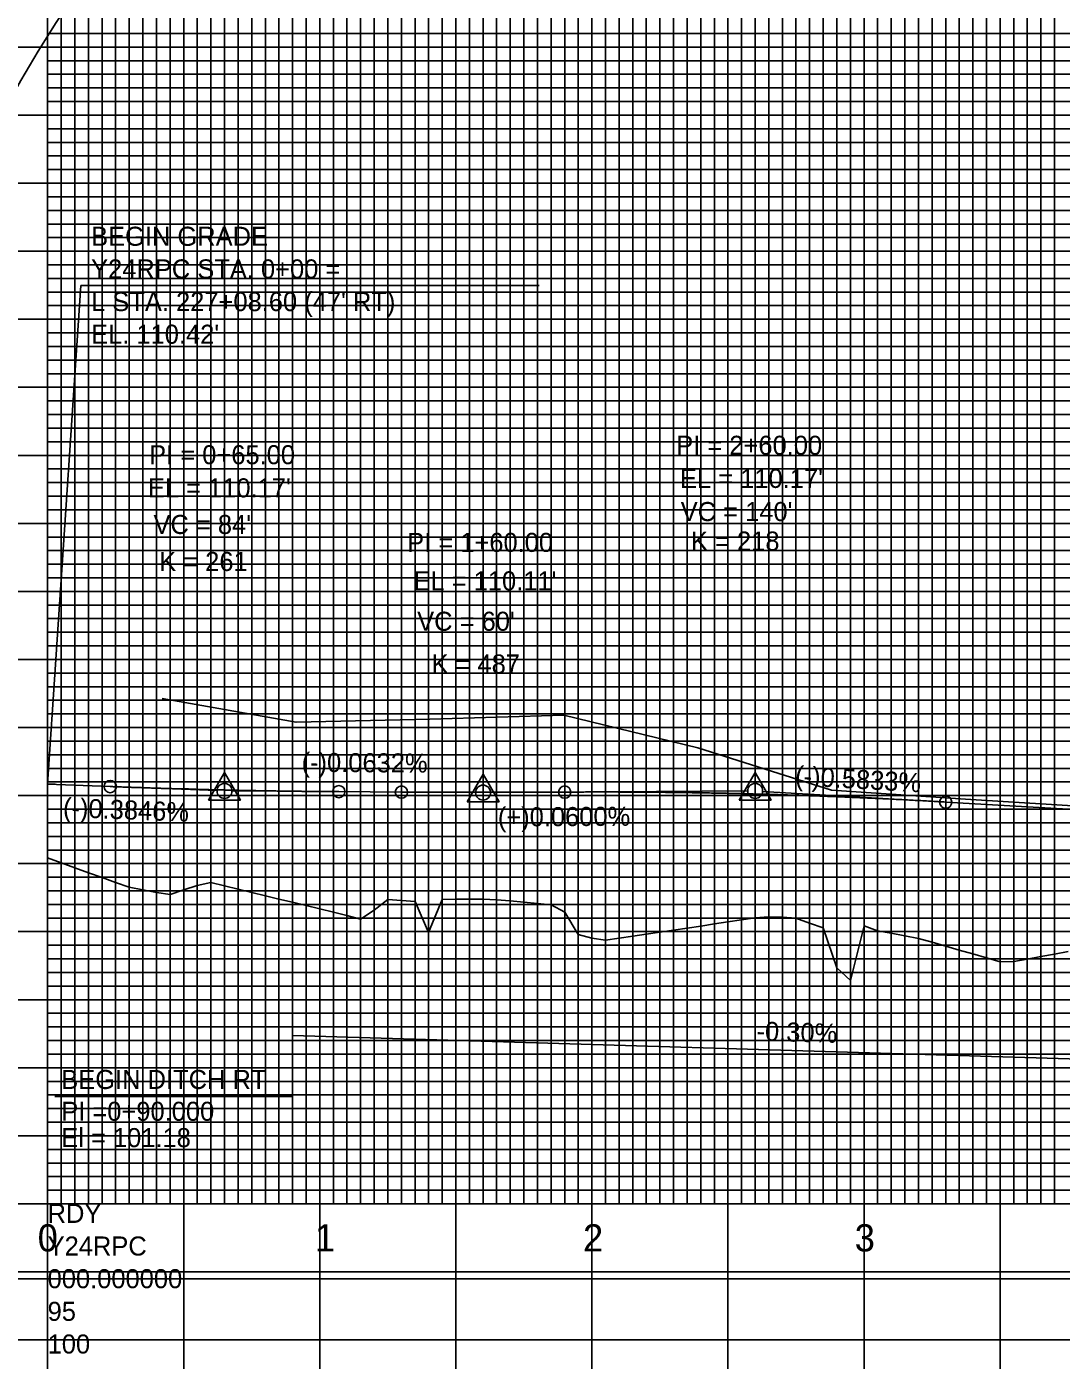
# Model space of a CAD drawing. Extents: x 2345490 to 2445302, y 465165 to 573888.
# Drawn here: x 2410887.6 to 2411267.8, y 527714.5 to 528204.5 of the extents above; entities that cross this region are included whole.
import ezdxf

# ---------------------------------------------------------------- set-up
doc = ezdxf.new("R2010")
doc.units = 0
for name, color, linetype in [('Old_Level_1', 7, 'Continuous'), ('Old_Level_18', 7, 'Continuous'), ('Old_Level_2', 7, 'Continuous'), ('Old_Level_3', 7, 'Continuous'), ('Old_Level_41', 7, 'Continuous'), ('Old_Level_42', 7, 'Continuous'), ('Old_Level_43', 7, 'Continuous'), ('Old_Level_50', 7, 'Continuous'), ('Old_Level_51', 7, 'Continuous'), ('Old_Level_62', 7, 'Continuous'), ('Old_Level_63', 7, 'Continuous')]:
    doc.layers.add(name, color=color, linetype=linetype)

msp = doc.modelspace()

# ---------------------------------------------------------------- linework, layer by layer
at = {"layer": 'Old_Level_1'}
msp.add_lwpolyline([(2410895.325, 527899.13175), (2410900.325, 527897.31625), (2410905.325, 527895.5035), (2410910.325, 527893.693), (2410915.325, 527891.885), (2410920.325, 527890.0795), (2410925.325, 527888.346), (2410930.325, 527887.3755), (2410935.325, 527886.411), (2410940.325, 527885.72725), (2410945.325, 527887.3925), (2410950.325, 527889.05825), (2410955.325, 527890.15175), (2410960.325, 527888.925), (2410965.325, 527887.7005), (2410970.325, 527886.47775), (2410975.325, 527885.2575), (2410980.325, 527884.03925), (2410985.325, 527882.82325), (2410990.325, 527881.60975), (2410995.325, 527880.3985), (2411000.325, 527879.18975), (2411005.325, 527877.93375), (2411010.325, 527876.6665), (2411015.325, 527879.893), (2411020.325, 527883.87575), (2411025.325, 527883.503), (2411030.325, 527883.133), (2411035.325, 527871.77675), (2411040.325, 527883.91325), (2411045.325, 527883.91925), (2411050.325, 527883.92525), (2411055.325, 527883.93125), (2411060.325, 527883.73025), (2411065.325, 527883.311), (2411070.325, 527882.85025), (2411075.325, 527882.393), (2411080.325, 527881.93875), (2411085.325, 527879.234), (2411090.325, 527871.036), (2411095.325, 527869.64375), (2411100.325, 527868.95075), (2411105.325, 527869.67875), (2411110.325, 527870.41), (2411115.325, 527871.145), (2411120.325, 527871.88325), (2411125.325, 527872.625), (2411130.325, 527873.37025), (2411135.325, 527874.119), (2411140.325, 527874.871), (2411145.325, 527875.6265), (2411150.325, 527876.38525), (2411155.325, 527877.1475), (2411160.325, 527877.43575), (2411165.325, 527877.34625), (2411170.325, 527876.95475), (2411175.325, 527875.21325), (2411180.325, 527873.416), (2411185.325, 527858.70475), (2411190.325, 527854.09575), (2411195.325, 527874.16475), (2411200.325, 527872.31375), (2411205.325, 527871.48075), (2411210.325, 527870.51025), (2411215.325, 527869.54075), (2411220.325, 527868.19025), (2411225.325, 527866.74475), (2411230.325, 527865.29575), (2411235.325, 527863.8435), (2411240.325, 527862.38775), (2411245.325, 527860.92875), (2411250.325, 527861.044), (2411255.325, 527861.95825), (2411260.325, 527862.8805), (2411265.325, 527863.81025), (2411270.325, 527864.748)], dxfattribs=at)
at = {"layer": 'Old_Level_18'}
msp.add_lwpolyline([(2412345.325, 528797.04275), (2410845.325, 528797.04275), (2410845.325, 527747.04275), (2412345.325, 527747.04275)], close=True, dxfattribs=at)
at = {"layer": 'Old_Level_2'}
for p, q in [((2410907.5385, 528109.43), (2410895.325, 527926.24275)), ((2411076.005, 528109.43), (2410907.5385, 528109.43)), ((2410895.325, 527926.243), (2410918.32525, 527925.3585)), ((2410918.32525, 527925.3585), (2410957.57725, 527923.84875)), ((2411002.325, 527923.47775), (2410963.075, 527923.72575)), ((2411002.325, 527923.47775), (2411025.325, 527923.3325)), ((2411025.325, 527923.3325), (2411052.57525, 527923.1605)), ((2411085.325, 527923.323), (2411152.57525, 527923.72675)), ((2411225.32525, 527919.65975), (2411158.0705, 527923.583)), ((2411085.325, 527923.323), (2411058.075, 527923.1595)), ((2411225.32525, 527919.65975), (2411300.325, 527915.28475))]:
    msp.add_line(p, q, dxfattribs=at)
for points in [[(2410954.45375, 527920.36775), (2410966.19625, 527920.36775), (2410960.32525, 527930.4935)], [(2411049.45375, 527919.76775), (2411061.19625, 527919.76775), (2411055.32525, 527929.8935)], [(2411149.45375, 527920.36775), (2411161.19625, 527920.36775), (2411155.32525, 527930.4935)]]:
    msp.add_lwpolyline(points, close=True, dxfattribs=at)
for centre, radius in [((2410918.32525, 527925.3585), 2.25), ((2410960.325, 527923.743), 2.75), ((2411002.325, 527923.47775), 2.25), ((2411025.325, 527923.3325), 2.25), ((2411055.325, 527923.143), 2.75), ((2411085.325, 527923.323), 2.25), ((2411155.325, 527923.743), 2.75), ((2411225.32525, 527919.65975), 2.25)]:
    msp.add_circle(centre, radius, dxfattribs=at)
for points in [[(2410918.32525, 527925.3585), (2410920.00525, 527925.2945), (2410921.68525, 527925.2315), (2410923.36525, 527925.1695), (2410925.04525, 527925.10875), (2410926.72525, 527925.049), (2410928.40525, 527924.99025), (2410930.08525, 527924.93275), (2410931.76525, 527924.87625), (2410933.44525, 527924.82075), (2410935.12525, 527924.76625), (2410936.80525, 527924.713), (2410938.48525, 527924.661), (2410940.16525, 527924.60975), (2410941.84525, 527924.55975), (2410943.52525, 527924.51075), (2410945.20525, 527924.463), (2410946.88525, 527924.416), (2410948.56525, 527924.3705), (2410950.24525, 527924.32575), (2410951.92525, 527924.28225), (2410953.60525, 527924.23975), (2410955.28525, 527924.19825), (2410956.96525, 527924.158), (2410958.64525, 527924.11875), (2410960.325, 527924.08075), (2410962.005, 527924.0435), (2410963.685, 527924.0075), (2410965.365, 527923.97275), (2410967.045, 527923.93875), (2410968.725, 527923.906), (2410970.405, 527923.8745), (2410972.085, 527923.84375), (2410973.765, 527923.81425), (2410975.445, 527923.786), (2410977.125, 527923.7585), (2410978.805, 527923.73225), (2410980.485, 527923.707), (2410982.165, 527923.683), (2410983.845, 527923.66), (2410985.525, 527923.638), (2410987.205, 527923.617), (2410988.885, 527923.59725), (2410990.565, 527923.5785), (2410992.245, 527923.561), (2410993.925, 527923.5445), (2410995.605, 527923.529), (2410997.285, 527923.5145), (2410998.965, 527923.50125), (2411000.645, 527923.489), (2411002.325, 527923.47775)], [(2411025.325, 527923.3325), (2411026.525, 527923.32525), (2411027.725, 527923.318), (2411028.925, 527923.31125), (2411030.125, 527923.30475), (2411031.325, 527923.2985), (2411032.525, 527923.2925), (2411033.725, 527923.28675), (2411034.925, 527923.2815), (2411036.125, 527923.27625), (2411037.325, 527923.2715), (2411038.525, 527923.267), (2411039.725, 527923.263), (2411040.925, 527923.259), (2411042.125, 527923.2555), (2411043.325, 527923.25225), (2411044.525, 527923.24925), (2411045.725, 527923.2465), (2411046.925, 527923.244), (2411048.125, 527923.242), (2411049.325, 527923.24025), (2411050.525, 527923.2385), (2411051.725, 527923.2375), (2411052.925, 527923.2365), (2411054.125, 527923.23575), (2411055.325, 527923.2355), (2411056.525, 527923.2355), (2411057.725, 527923.23575), (2411058.925, 527923.23625), (2411060.125, 527923.237), (2411061.325, 527923.23825), (2411062.525, 527923.23975), (2411063.725, 527923.2415), (2411064.925, 527923.2435), (2411066.125, 527923.24575), (2411067.325, 527923.2485), (2411068.525, 527923.25125), (2411069.725, 527923.2545), (2411070.925, 527923.258), (2411072.125, 527923.26175), (2411073.325, 527923.266), (2411074.525, 527923.27025), (2411075.725, 527923.275), (2411076.925, 527923.28), (2411078.125, 527923.28525), (2411079.325, 527923.29075), (2411080.525, 527923.29675), (2411081.725, 527923.30275), (2411082.925, 527923.30925), (2411084.125, 527923.316), (2411085.325, 527923.323)], [(2411085.325, 527923.323), (2411088.125, 527923.338), (2411090.925, 527923.3495), (2411093.725, 527923.35725), (2411096.525, 527923.3615), (2411099.325, 527923.362), (2411102.125, 527923.359), (2411104.925, 527923.3525), (2411107.725, 527923.34225), (2411110.525, 527923.3285), (2411113.325, 527923.311), (2411116.125, 527923.29), (2411118.925, 527923.26525), (2411121.725, 527923.237), (2411124.525, 527923.20525), (2411127.325, 527923.16975), (2411130.125, 527923.13075), (2411132.925, 527923.08825), (2411135.725, 527923.042), (2411138.525, 527922.992), (2411141.325, 527922.9385), (2411144.125, 527922.8815), (2411146.925, 527922.821), (2411149.725, 527922.7565), (2411152.525, 527922.68875), (2411155.325, 527922.61725), (2411158.12525, 527922.54225), (2411160.92525, 527922.4635), (2411163.72525, 527922.38125), (2411166.52525, 527922.2955), (2411169.32525, 527922.206), (2411172.12525, 527922.11275), (2411174.92525, 527922.01625), (2411177.72525, 527921.91575), (2411180.52525, 527921.812), (2411183.32525, 527921.7045), (2411186.12525, 527921.5935), (2411188.92525, 527921.47875), (2411191.72525, 527921.3605), (2411194.52525, 527921.2385), (2411197.32525, 527921.113), (2411200.12525, 527920.984), (2411202.92525, 527920.85125), (2411205.72525, 527920.71475), (2411208.52525, 527920.575), (2411211.32525, 527920.4315), (2411214.12525, 527920.28425), (2411216.92525, 527920.1335), (2411219.72525, 527919.97925), (2411222.52525, 527919.82125), (2411225.32525, 527919.65975)]]:
    msp.add_spline(points, degree=3, dxfattribs=at)
at = {"layer": 'Old_Level_3'}
for p, q in [((2410895.325, 527772.04275), (2410895.325, 527842.4422)), ((2410895.325, 527842.4422), (2410895.325, 527600.73736)), ((2410985.325, 527833.84275), (2411407.325, 527821.24275)), ((2410985.325, 527833.84275), (2410985.32509, 527811.44435)), ((2410897.96027, 527811.44435), (2410985.32509, 527811.44435))]:
    msp.add_line(p, q, dxfattribs=at)
at = {"layer": 'Old_Level_41'}
msp.add_line((2412345.325, 527772.04275), (2410845.325, 527772.04275), dxfattribs=at)
for points in [[(2410895.325, 528797.04275), (2410895.325, 527772.04275), (2410945.325, 527772.04275), (2410945.325, 528797.04275)], [(2410920.325, 527772.04275), (2410920.325, 528797.04275)], [(2410970.325, 528797.04275), (2410970.325, 527772.04275), (2411020.325, 527772.04275), (2411020.325, 528797.04275)], [(2410995.325, 528797.04275), (2410995.325, 527772.04275), (2411045.325, 527772.04275), (2411045.325, 528797.04275)], [(2411070.325, 528797.04275), (2411070.325, 527772.04275), (2411120.325, 527772.04275), (2411120.325, 528797.04275)], [(2411095.325, 528797.04275), (2411095.325, 527772.04275), (2411145.325, 527772.04275), (2411145.325, 528797.04275)], [(2411170.325, 528797.04275), (2411170.325, 527772.04275), (2411220.325, 527772.04275), (2411220.325, 528797.04275)], [(2411195.325, 528797.04275), (2411195.325, 527772.04275), (2411245.325, 527772.04275), (2411245.325, 528797.04275)], [(2412345.325, 528197.04275), (2410845.325, 528197.04275), (2410845.325, 528147.04275), (2412345.325, 528147.04275)], [(2412345.325, 528122.04275), (2410845.325, 528122.04275), (2410845.325, 528172.04275), (2412345.325, 528172.04275)], [(2412345.325, 528097.04275), (2410845.325, 528097.04275), (2410845.325, 528047.04275), (2412345.325, 528047.04275)], [(2412345.325, 528022.04275), (2410845.325, 528022.04275), (2410845.325, 528072.04275), (2412345.325, 528072.04275)], [(2412345.325, 527997.04275), (2410845.325, 527997.04275), (2410845.325, 527947.04275), (2412345.325, 527947.04275)], [(2412345.325, 527897.04275), (2410845.325, 527897.04275), (2410845.325, 527847.04275), (2412345.325, 527847.04275)], [(2412345.325, 527822.04275), (2410845.325, 527822.04275), (2410845.325, 527872.04275), (2412345.325, 527872.04275)], [(2412345.325, 527797.04275), (2410845.325, 527797.04275)]]:
    msp.add_lwpolyline(points, dxfattribs=at)
at = {"layer": 'Old_Level_42'}
msp.add_lwpolyline([(2412345.325, 527922.04275), (2410845.325, 527922.04275), (2410845.325, 527972.04275), (2412345.325, 527972.04275)], dxfattribs=at)
at = {"layer": 'Old_Level_43'}
for points in [[(2410900.325, 528797.04275), (2410900.325, 527772.04275), (2410905.325, 527772.04275), (2410905.325, 528797.04275)], [(2410910.325, 528797.04275), (2410910.325, 527772.04275), (2410915.325, 527772.04275), (2410915.325, 528797.04275)], [(2410925.325, 528797.04275), (2410925.325, 527772.04275), (2410930.325, 527772.04275), (2410930.325, 528797.04275)], [(2410935.325, 528797.04275), (2410935.325, 527772.04275), (2410940.325, 527772.04275), (2410940.325, 528797.04275)], [(2410950.325, 528797.04275), (2410950.325, 527772.04275), (2410955.325, 527772.04275), (2410955.325, 528797.04275)], [(2410960.325, 528797.04275), (2410960.325, 527772.04275), (2410965.325, 527772.04275), (2410965.325, 528797.04275)], [(2410975.325, 528797.04275), (2410975.325, 527772.04275), (2410980.325, 527772.04275), (2410980.325, 528797.04275)], [(2410985.325, 528797.04275), (2410985.325, 527772.04275), (2410990.325, 527772.04275), (2410990.325, 528797.04275)], [(2411000.325, 528797.04275), (2411000.325, 527772.04275), (2411005.325, 527772.04275), (2411005.325, 528797.04275)], [(2411010.325, 528797.04275), (2411010.325, 527772.04275), (2411015.325, 527772.04275), (2411015.325, 528797.04275)], [(2411025.325, 528797.04275), (2411025.325, 527772.04275), (2411030.325, 527772.04275), (2411030.325, 528797.04275)], [(2411035.325, 528797.04275), (2411035.325, 527772.04275), (2411040.325, 527772.04275), (2411040.325, 528797.04275)], [(2411050.325, 528797.04275), (2411050.325, 527772.04275), (2411055.325, 527772.04275), (2411055.325, 528797.04275)], [(2411060.325, 527772.04275), (2411065.325, 527772.04275), (2411065.325, 528797.04275)], [(2411060.325, 528797.04275), (2411060.325, 527772.04275)], [(2411075.325, 528797.04275), (2411075.325, 527772.04275), (2411080.325, 527772.04275), (2411080.325, 528797.04275)], [(2411085.325, 528797.04275), (2411085.325, 527772.04275), (2411090.325, 527772.04275), (2411090.325, 528797.04275)], [(2411100.325, 528797.04275), (2411100.325, 527772.04275), (2411105.325, 527772.04275), (2411105.325, 528797.04275)], [(2411110.325, 528797.04275), (2411110.325, 527772.04275), (2411115.325, 527772.04275), (2411115.325, 528797.04275)], [(2411125.325, 528797.04275), (2411125.325, 527772.04275), (2411130.325, 527772.04275), (2411130.325, 528797.04275)], [(2411135.325, 528797.04275), (2411135.325, 527772.04275), (2411140.325, 527772.04275), (2411140.325, 528797.04275)], [(2411150.325, 528797.04275), (2411150.325, 527772.04275), (2411155.325, 527772.04275), (2411155.325, 528797.04275)], [(2411160.325, 528797.04275), (2411160.325, 527772.04275), (2411165.325, 527772.04275), (2411165.325, 528797.04275)], [(2411175.325, 528797.04275), (2411175.325, 527772.04275), (2411180.325, 527772.04275), (2411180.325, 528797.04275)], [(2411185.325, 528797.04275), (2411185.325, 527772.04275), (2411190.325, 527772.04275), (2411190.325, 528797.04275)], [(2411200.325, 528797.04275), (2411200.325, 527772.04275), (2411205.325, 527772.04275), (2411205.325, 528797.04275)], [(2411210.325, 528797.04275), (2411210.325, 527772.04275), (2411215.325, 527772.04275), (2411215.325, 528797.04275)], [(2411225.325, 528797.04275), (2411225.325, 527772.04275), (2411240.325, 527772.04275), (2411240.325, 528797.04275)], [(2411230.325, 528797.04275), (2411230.325, 527772.04275), (2411235.325, 527772.04275), (2411235.325, 528797.04275)], [(2411230.325, 528796.44275), (2411230.325, 527772.04275), (2411235.325, 527772.04275), (2411235.325, 528796.44275)], [(2411250.325, 528797.04275), (2411250.325, 527772.04275), (2411255.325, 527772.04275), (2411255.325, 528797.04275)], [(2411260.325, 528797.04275), (2411260.325, 527772.04275), (2411265.325, 527772.04275), (2411265.325, 528797.04275)], [(2412295.325, 528202.04275), (2410895.325, 528202.04275), (2410895.325, 528192.04275), (2412295.325, 528192.04275)], [(2412295.325, 528187.04275), (2410895.325, 528187.04275), (2410895.325, 528182.04275), (2412295.325, 528182.04275)], [(2412295.325, 528177.04275), (2410895.325, 528177.04275), (2410895.325, 528167.04275), (2412295.325, 528167.04275)], [(2412295.325, 528162.04275), (2410895.325, 528162.04275), (2410895.325, 528157.04275), (2412295.325, 528157.04275)], [(2412295.325, 528152.04275), (2410895.325, 528152.04275), (2410895.325, 528142.04275), (2412295.325, 528142.04275)], [(2412295.325, 528137.04275), (2410895.325, 528137.04275), (2410895.325, 528132.04275), (2412295.325, 528132.04275)], [(2412295.325, 528127.04275), (2410895.325, 528127.04275), (2410895.325, 528117.04275), (2412295.325, 528117.04275)], [(2412295.325, 528112.04275), (2410895.325, 528112.04275), (2410895.325, 528107.04275), (2412295.325, 528107.04275)], [(2412295.325, 528102.04275), (2410895.325, 528102.04275), (2410895.325, 528092.04275), (2412295.325, 528092.04275)], [(2412295.325, 528087.04275), (2410895.325, 528087.04275), (2410895.325, 528082.04275), (2412295.325, 528082.04275)], [(2412295.325, 528077.04275), (2410895.325, 528077.04275), (2410895.325, 528067.04275), (2412295.325, 528067.04275)], [(2412295.325, 528062.04275), (2410895.325, 528062.04275), (2410895.325, 528057.04275), (2412295.325, 528057.04275)], [(2412295.325, 528052.04275), (2410895.325, 528052.04275), (2410895.325, 528042.04275), (2412295.325, 528042.04275)], [(2412295.325, 528037.04275), (2410895.325, 528037.04275), (2410895.325, 528032.04275), (2412295.325, 528032.04275)], [(2412295.325, 528027.04275), (2410895.325, 528027.04275), (2410895.325, 528017.04275), (2412295.325, 528017.04275)], [(2412295.325, 528012.04275), (2410895.325, 528012.04275), (2410895.325, 528007.04275), (2412295.325, 528007.04275)], [(2412295.325, 528002.04275), (2410895.325, 528002.04275), (2410895.325, 527992.04275), (2412295.325, 527992.04275)], [(2412295.325, 527987.04275), (2410895.325, 527987.04275), (2410895.325, 527982.04275), (2412295.325, 527982.04275)], [(2412295.325, 527977.04275), (2410895.325, 527977.04275)], [(2410895.325, 527967.04275), (2412295.325, 527967.04275)], [(2412295.325, 527962.04275), (2410895.325, 527962.04275), (2410895.325, 527957.04275), (2412295.325, 527957.04275)], [(2412295.325, 527952.04275), (2410895.325, 527952.04275)], [(2410895.325, 527942.04275), (2412295.325, 527942.04275)], [(2412295.325, 527937.04275), (2410895.325, 527937.04275), (2410895.325, 527932.04275), (2412295.325, 527932.04275)], [(2412295.325, 527927.04275), (2410895.325, 527927.04275), (2410895.325, 527917.04275), (2412295.325, 527917.04275)], [(2412295.325, 527912.04275), (2410895.325, 527912.04275), (2410895.325, 527907.04275), (2412295.325, 527907.04275)], [(2412295.325, 527902.04275), (2410895.325, 527902.04275), (2410895.325, 527892.04275), (2412295.325, 527892.04275)], [(2412295.325, 527887.04275), (2410895.325, 527887.04275), (2410895.325, 527882.04275), (2412295.325, 527882.04275)], [(2412295.325, 527877.04275), (2410895.325, 527877.04275), (2410895.325, 527867.04275), (2412295.325, 527867.04275)], [(2412295.325, 527862.04275), (2410895.325, 527862.04275), (2410895.325, 527857.04275), (2412295.325, 527857.04275)], [(2412295.325, 527852.04275), (2410895.325, 527852.04275), (2410895.325, 527842.04275), (2412295.325, 527842.04275)], [(2412295.325, 527837.04275), (2410895.325, 527837.04275), (2410895.325, 527832.04275), (2412295.325, 527832.04275)], [(2412295.325, 527827.04275), (2410895.325, 527827.04275), (2410895.325, 527817.04275), (2412295.325, 527817.04275)], [(2412295.325, 527812.04275), (2410895.325, 527812.04275), (2410895.325, 527807.04275), (2412295.325, 527807.04275)], [(2412295.325, 527802.04275), (2410895.325, 527802.04275), (2410895.325, 527792.04275), (2412295.325, 527792.04275)], [(2412295.325, 527787.04275), (2410895.325, 527787.04275), (2410895.325, 527782.04275), (2412295.325, 527782.04275)], [(2412295.325, 527777.04275), (2410895.325, 527777.04275)]]:
    msp.add_lwpolyline(points, dxfattribs=at)
at = {"layer": 'Old_Level_50'}
msp.add_lwpolyline([(2412357.825, 528799.59275), (2410691.325, 528799.59275), (2410691.325, 527744.49275), (2412357.825, 527744.49275)], close=True, dxfattribs=at)
at = {"layer": 'Old_Level_51'}
msp.add_lwpolyline([(2412362.325, 528822.04275), (2410678.325, 528822.04275), (2410678.325, 527722.04275), (2412362.325, 527722.04275)], close=True, dxfattribs=at)
at = {"layer": 'Old_Level_62'}
msp.add_circle((2411335.51705, 527926.51577), 518.74216, dxfattribs=at)
at = {"layer": 'Old_Level_63'}
for p, q in [((2410895.325, 527772.04275), (2410895.325, 530272.04275)), ((2411145.325, 527924.50275), (2411145.325, 528076.15275)), ((2411195.325, 527925.04275), (2411195.325, 528076.15275)), ((2411245.325, 527924.23275), (2411245.325, 528076.15275)), ((2410895.325, 527926.25275), (2410898.048, 527926.25275)), ((2410895.325, 527926.24275), (2410895.325, 527564.29475)), ((2410895.325, 527926.23275), (2410898.048, 527926.23275)), ((2410945.325, 527924.47275), (2410947.06075, 527924.47275)), ((2410945.325, 527924.46275), (2410945.325, 527564.29475)), ((2410945.325, 527924.45275), (2410947.06075, 527924.45275)), ((2410995.325, 527923.54275), (2410999.9535, 527923.54275)), ((2410995.325, 527923.53275), (2410995.325, 527564.29475)), ((2410995.325, 527923.52275), (2410999.9535, 527923.52275)), ((2411095.325, 527923.36275), (2411095.331, 527923.36275)), ((2411095.325, 527923.35275), (2411095.325, 527564.29475)), ((2411095.325, 527923.34275), (2411095.331, 527923.34275)), ((2411045.325, 527923.25275), (2411047.927, 527923.25275)), ((2411045.325, 527923.24275), (2411045.325, 527564.29475)), ((2411045.325, 527923.23275), (2411047.927, 527923.23275)), ((2411145.325, 527922.52275), (2411145.325, 527564.29475)), ((2411195.325, 527919.28275), (2411195.325, 527564.29475)), ((2411245.325, 527913.62275), (2411245.325, 527564.29475)), ((2410895.325, 527772.04275), (2413081.64925, 527772.04275)), ((2410895.325, 527772.04275), (2410895.325, 525272.04275))]:
    msp.add_line(p, q, dxfattribs=at)
msp.add_lwpolyline([(2410937.46001, 527957.6808), (2410986.64001, 527948.9808), (2411035.83001, 527950.0808), (2411085.01001, 527951.5808), (2411134.21001, 527939.5808), (2411183.43001, 527923.9808), (2411232.67001, 527920.7808), (2411281.95001, 527917.6808), (2411331.27001, 527914.4808), (2411380.65001, 527911.1808), (2411426.73001, 527909.8808), (2411471.73001, 527905.9808), (2411521.73001, 527907.3808), (2411571.73001, 527908.8808), (2411616.73001, 527910.2808), (2411666.73001, 527911.7808), (2411716.73001, 527939.3808), (2411746.73001, 527928.4808), (2411796.73001, 527927.4808), (2411846.73001, 527909.0808)], dxfattribs=at)

# ---------------------------------------------------------------- texts
at = {"layer": 'Old_Level_2'}
for s, height, p in [('BEGIN GRADE', 7.0000005, (2410911.29775, 528124.0405)), ('Y24RPC STA. 0+00 =', 7.0000005, (2410911.29775, 528112.0405)), ("L STA. 227+08.60 (47' RT)", 7.0000005, (2410911.29775, 528100.0405)), ("EL. 110.42'", 7.0000005, (2410911.29775, 528088.0405)), ('PI = 0+65.00', 7.0000005, (2410932.625, 528043.77875)), ('PI = 2+60.00', 7.0000005, (2411126.325, 528047.243)), ("EL = 110.17'", 7.0000005, (2411127.705, 528035.065)), ("EL = 110.17'", 7.0000005, (2410932.165, 528031.6005)), ("VC = 140'", 7.000001, (2411127.9535, 528022.89475)), ("VC = 84'", 7.000001, (2410934.21675, 528018.156)), ('PI = 1+60.00', 7.0000005, (2411027.44825, 528011.5675)), ('K = 218', 7.000001, (2411131.7435, 528012.0395)), ('K = 261', 7.000001, (2410936.3225, 528004.56275)), ("EL = 110.11'", 7.0000005, (2411029.76425, 527997.43225)), ("VC = 60'", 7.000001, (2411031.11175, 527982.59025)), ('K = 487', 7.000001, (2411036.3755, 527966.89075))]:
    msp.add_text(s, height=height, dxfattribs=at).set_placement(p)
for s, rotation, p in [('(-)0.0632%', 359.6381361, (2410988.63075, 527930.75925)), ('(-)0.5833%', 356.6615306, (2411169.851, 527925.901)), ('(-)0.3846%', 357.7974028, (2410900.874, 527914.19575)), ('(+)0.0600%', 0.3437694, (2411060.7785, 527910.667))]:
    msp.add_text(s, height=7.000001, rotation=rotation, dxfattribs=at).set_placement(p)
at = {"layer": 'Old_Level_3'}
for s, height, rotation, p in [('-0.30%', 7.000001, 358.2897807, (2411155.73571, 527832.04891)), ('BEGIN DITCH RT', 7.0000005, 360, (2410900.3286, 527814.24203)), ('PI =0+90.000', 7.0000005, 360, (2410900.3286, 527802.54268)), ('El = 101.18', 7.0000005, 360, (2410900.3286, 527792.87215))]:
    msp.add_text(s, height=height, rotation=rotation, dxfattribs=at).set_placement(p)
at = {"layer": 'Old_Level_62'}
for s, p in [('0', (2410891.666, 527754.543)), ('1', (2410993.5055, 527754.543)), ('2', (2411092.054, 527754.543)), ('3', (2411191.88875, 527754.543))]:
    msp.add_text(s, height=10, dxfattribs=at).set_placement(p)
at = {"layer": 'Old_Level_63'}
for s, p in [('RDY', (2410895.325, 527765.04275)), ('Y24RPC', (2410895.325, 527753.04275)), ('000.000000', (2410895.325, 527741.04275)), ('95', (2410895.325, 527729.04275)), ('100', (2410895.325, 527717.04275))]:
    msp.add_text(s, height=7.000001, dxfattribs=at).set_placement(p)

doc.saveas('drawing.dxf')
